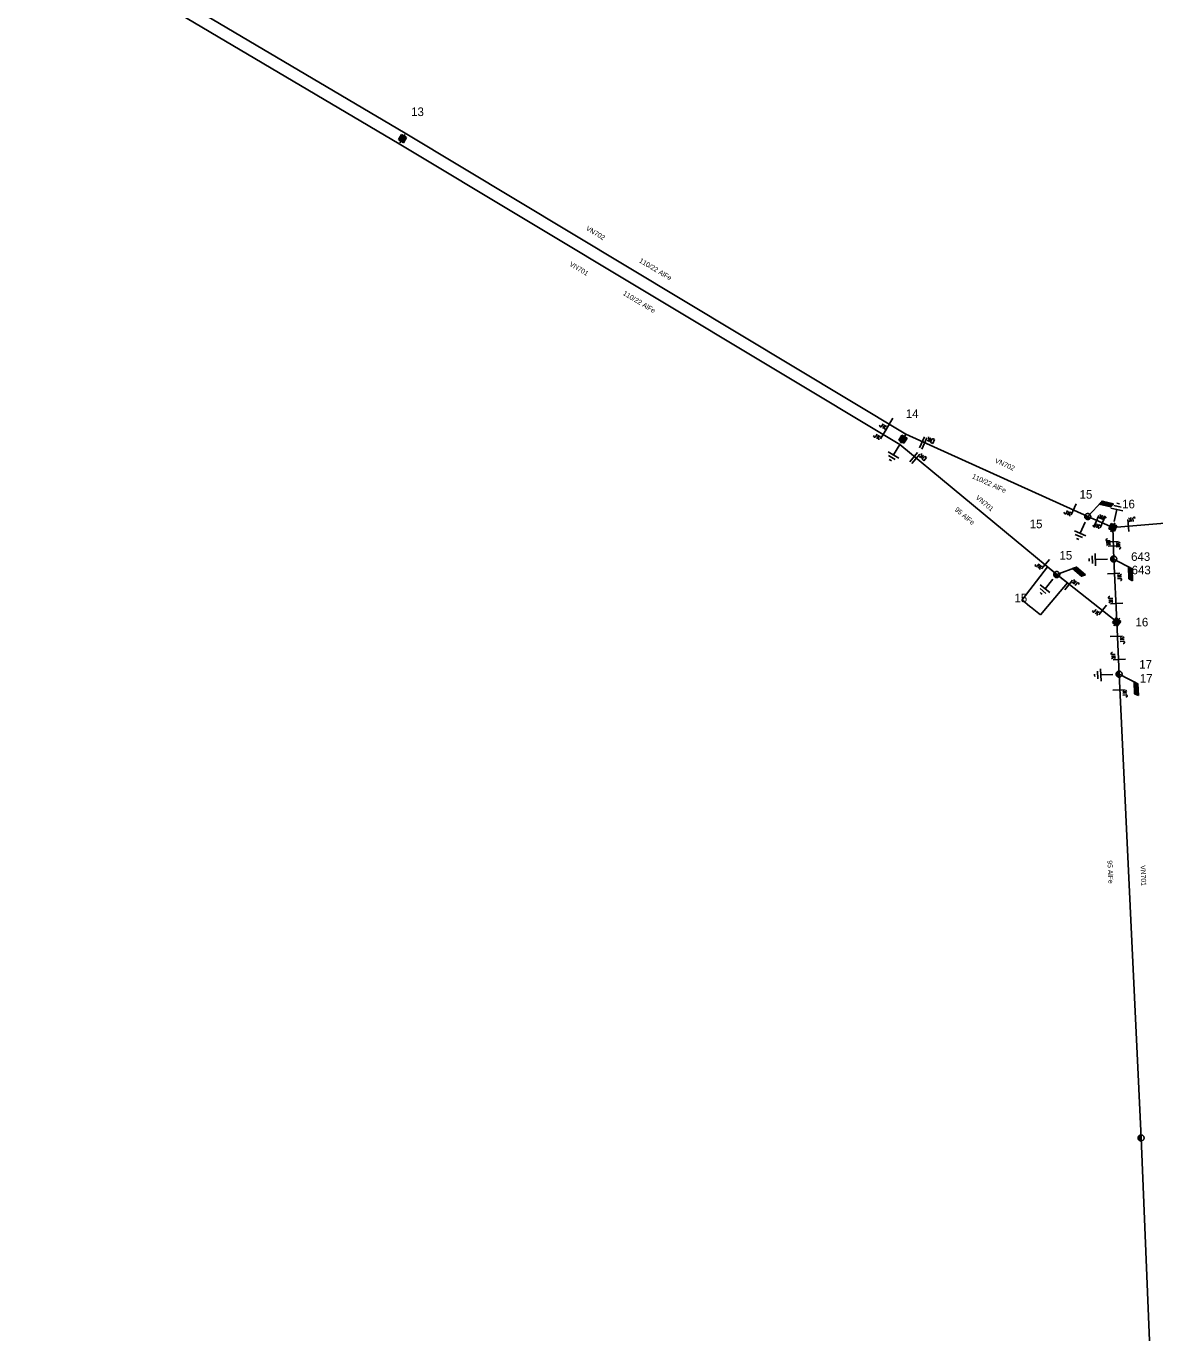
# Model space of a CAD drawing. Extents: x -545588 to -543214, y -1196037 to -1194452.
# Drawn here: x -543827.7 to -543597.4, y -1196037.4 to -1195769.1 of the extents above; entities that cross this region are included whole.
import ezdxf

# ---------------------------------------------------------------- set-up
doc = ezdxf.new("R2010")
doc.units = 0
for name, color, linetype in [('Default', 7, 'Continuous'), ('Vrstva 1', 7, 'Continuous'), ('Vrstva 11', 7, 'Continuous'), ('Vrstva 12', 7, 'Continuous'), ('Vrstva 13', 7, 'Continuous'), ('Vrstva 14', 7, 'Continuous'), ('Vrstva 15', 7, 'Continuous'), ('Vrstva 18', 7, 'Continuous'), ('Vrstva 2', 7, 'Continuous'), ('Vrstva 3', 7, 'Continuous'), ('Vrstva 35', 7, 'Continuous'), ('Vrstva 52', 7, 'Continuous')]:
    doc.layers.add(name, color=color, linetype=linetype)

# ---------------------------------------------------------------- blocks, each defined once
blk = doc.blocks.new('VN850')
at = {"layer": 'Vrstva 15'}
for points in [[(-0.56, 1.43), (-0.56, -1.07)], [(-0.01, 1.43), (-0.01, -1.07)], [(-2.09, -0.54), (-1.78, -0.54)], [(-2.09, -1.41), (-2.09, -0.54)], [(-1.78, -1.41), (-2.09, -1.41)], [(-1.78, -0.54), (-1.66, -0.6)], [(-1.67, -1.35), (-1.78, -1.41)], [(-1.59, -1.2), (-1.67, -1.35)], [(-1.66, -0.6), (-1.59, -0.75)], [(-1.59, -0.75), (-1.55, -0.96)], [(-1.55, -0.96), (-1.59, -1.2)], [(-1.26, -0.54), (-1.26, -1.41)], [(-0.85, -0.54), (-1.26, -1.09)], [(-1.13, -0.92), (-0.77, -1.41)]]:
    blk.add_lwpolyline(points, dxfattribs=at)
blk = doc.blocks.new('VN840')
at = {"layer": 'Vrstva 15'}
for points in [[(-0.01, 1.41), (-0.01, -1.09)], [(-1.51, -1.24), (-1.51, -1.15)], [(-1.48, -1.35), (-1.51, -1.24)], [(-1.33, -1.42), (-1.48, -1.35)], [(-1.27, -1.42), (-1.33, -1.42)], [(-1.13, -1.35), (-1.27, -1.42)], [(-1.09, -1.24), (-1.13, -1.35)], [(-1.09, -0.59), (-1.09, -1.24)], [(-0.68, -0.59), (-0.68, -1.42)], [(-0.68, -1.11), (-0.27, -0.59)], [(-0.54, -0.94), (-0.2, -1.42)]]:
    blk.add_lwpolyline(points, dxfattribs=at)
blk = doc.blocks.new('VN440')
at = {"layer": 'Vrstva 2'}
for points in [[(1.22, 0), (1.21, 0.13), (1.19, 0.25), (1.16, 0.38), (1.11, 0.5), (1.05, 0.61), (0.98, 0.72), (0.9, 0.82), (0.81, 0.91), (0.71, 0.99), (0.6, 1.06), (0.49, 1.12), (0.37, 1.16), (0.25, 1.2), (0.12, 1.22), (-0.01, 1.22), (-0.14, 1.22), (-0.26, 1.2), (-0.39, 1.16), (-0.51, 1.12), (-0.62, 1.06), (-0.73, 0.99), (-0.83, 0.91), (-0.92, 0.82), (-1, 0.72), (-1.07, 0.61), (-1.13, 0.5), (-1.18, 0.38), (-1.21, 0.25), (-1.23, 0.13), (-1.24, 0), (-1.23, -0.13), (-1.21, -0.26), (-1.18, -0.38), (-1.13, -0.5), (-1.07, -0.62), (-1, -0.73), (-0.92, -0.83), (-0.83, -0.92), (-0.73, -1), (-0.62, -1.07), (-0.51, -1.13), (-0.39, -1.17), (-0.26, -1.2), (-0.14, -1.23), (-0.01, -1.23), (0.12, -1.23), (0.25, -1.2), (0.37, -1.17), (0.49, -1.13), (0.6, -1.07), (0.71, -1), (0.81, -0.92), (0.9, -0.83), (0.98, -0.73), (1.05, -0.62), (1.11, -0.5), (1.16, -0.38), (1.19, -0.26), (1.21, -0.13), (1.22, 0)], [(-1.24, 0), (1.22, 0)], [(-1.18, -0.34), (1.1, -0.34)], [(-1.01, -0.63), (0.97, -0.63)], [(-0.74, -0.92), (0.68, -0.92)]]:
    blk.add_lwpolyline(points, dxfattribs=at)
blk = doc.blocks.new('VN810')
at = {"layer": 'Vrstva 14'}
for points in [[(0, -1.25), (0, -3.75)], [(1.25, -3.75), (-1.25, -3.75)], [(0.77, -4.37), (-0.8, -4.37)], [(0, -5), (-0.25, -5)], [(0.27, -5), (0, -5)]]:
    blk.add_lwpolyline(points, dxfattribs=at)
blk = doc.blocks.new('VN001')
at = {"layer": 'Default'}
for p, q in [((1.73, 3.03), (4.14, 3.03)), ((1.76, 3.08), (4.17, 3.08)), ((1.79, 3.13), (4.2, 3.13)), ((1.82, 3.18), (4.23, 3.18)), ((1.85, 3.23), (4.26, 3.23)), ((1.87, 3.28), (4.29, 3.28)), ((1.9, 3.33), (4.32, 3.33)), ((1.93, 3.38), (4.35, 3.38)), ((1.96, 3.43), (4.37, 3.43)), ((1.99, 3.48), (4.4, 3.48)), ((2.02, 3.53), (4.43, 3.53)), ((2.05, 3.58), (4.46, 3.58)), ((2.07, 3.63), (4.49, 3.63)), ((2.1, 3.68), (4.52, 3.68)), ((2.13, 3.73), (2.54, 3.73))]:
    blk.add_line(p, q, dxfattribs=at)
blk.add_lwpolyline([(2.13, 3.73), (0, 0)], dxfattribs=at)
blk.add_lwpolyline([(4.55, 3.73), (2.13, 3.73), (1.7, 2.98), (4.12, 2.99)], close=True, dxfattribs=at)
blk = doc.blocks.new('VN470')
at = {"layer": 'Vrstva 2'}
for points in [[(-1.23, 1.22), (1.23, 1.22)], [(-1.23, -1.23), (-1.23, 1.22)], [(-0.92, 0.9), (0.92, 0.9)], [(-0.92, -0.95), (-0.92, 0.9)], [(-0.61, 0.61), (0.61, 0.61)], [(-0.61, -0.62), (-0.61, 0.61)], [(-0.31, -0.27), (-0.31, 0.34)], [(-0.31, 0.34), (0.31, 0.34)], [(0, 1.22), (0, 1.97)], [(0.31, 0.34), (0.31, -0.27)], [(0.61, 0.61), (0.61, -0.62)], [(0.92, 0.9), (0.92, -0.95)], [(1.23, 1.22), (1.23, -1.23)], [(1.23, -1.23), (-1.23, -1.23)], [(0.92, -0.95), (-0.92, -0.95)], [(0.61, -0.62), (-0.61, -0.62)], [(0.31, -0.27), (-0.31, -0.27)], [(0, -1.23), (0, -1.98)]]:
    blk.add_lwpolyline(points, dxfattribs=at)

msp = doc.modelspace()

# ---------------------------------------------------------------- linework, layer by layer
at = {"layer": 'Vrstva 1'}
for points in [[(-545087.98, -1194964.09), (-544969.35, -1195068.41), (-544833.03, -1195149.76), (-544688.41, -1195235.46), (-544556.36, -1195314.32), (-544420.24, -1195394.62), (-544279.84, -1195477.88), (-544141.02, -1195559.94), (-544005.67, -1195639.57), (-543873.94, -1195717.89), (-543750.35, -1195790.92), (-543648.17, -1195852.31)], [(-543649.39, -1195854.44), (-543751.62, -1195793.1), (-543875.2, -1195719.97), (-544006.92, -1195641.71), (-544142.24, -1195562.12), (-544281.11, -1195480), (-544421.5, -1195396.73), (-544557.6, -1195316.44), (-544689.64, -1195237.57), (-544834.28, -1195151.89), (-544970.6, -1195070.55), (-545089.61, -1194965.95)], [(-543605.91, -1195871.36), (-543527.67, -1195864.84), (-543432.77, -1195857.32), (-543323.46, -1195848.64), (-543214.01, -1195839.86)], [(-543648.17, -1195852.31), (-543611.03, -1195869.16)], [(-543617.36, -1195881), (-543649.39, -1195854.44)], [(-543611.03, -1195869.16), (-543605.91, -1195871.36)], [(-543605.11, -1195890.68), (-543617.36, -1195881)], [(-543604.63, -1195901.33), (-543605.11, -1195890.68)], [(-543598.42, -1196037.4), (-543600.15, -1195996.01), (-543604.63, -1195901.33)]]:
    msp.add_lwpolyline(points, dxfattribs=at)
at = {"layer": 'Vrstva 35'}
msp.add_lwpolyline([(-543620.7, -1195889.19), (-543622.71, -1195887.61), (-543622.84, -1195887.5), (-543624.45, -1195886.17), (-543619.23, -1195879.45), (-543617.36, -1195881), (-543615.19, -1195882.72), (-543619.26, -1195887.5)], close=True, dxfattribs=at)
at = {"layer": 'Vrstva 52'}
for points in [[(-543605.91, -1195871.36), (-543605.73, -1195877.83)], [(-543605.73, -1195877.83), (-543605.11, -1195890.68)]]:
    msp.add_lwpolyline(points, dxfattribs=at)

# ---------------------------------------------------------------- block references
at = {"layer": 'Vrstva 11'}
for p, rotation in [((-543611.03, -1195869.16), -13.05202785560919), ((-543617.36, -1195881), -39.670955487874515), ((-543605.73, -1195877.83), -88.40301664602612), ((-543604.63, -1195901.33), -87.43911945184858)]:
    msp.add_blockref('VN001', p, dxfattribs=dict(at, rotation=rotation))
at = {"layer": 'Vrstva 13'}
for name, p, xscale, yscale, rotation in [('VN470', (-543750.92, -1195792), 0.49999999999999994, 0.5, 149.0160277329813), ('VN470', (-543648.75, -1195853.35), 0.5, 0.5, -30.98348877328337), ('VN440', (-543611.03, -1195869.16), 0.5, 0.5, -24.396491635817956), ('VN470', (-543605.91, -1195871.36), 0.5, 0.5, -23.261608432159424), ('VN440', (-543605.73, -1195877.83), 0.49999999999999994, 0.5, -88.40873060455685), ('VN440', (-543617.36, -1195881), 0.5, 0.5, -39.67067774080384), ('VN470', (-543605.11, -1195890.68), 0.49999999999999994, 0.5000000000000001, -38.31669718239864), ('VN440', (-543604.63, -1195901.33), 0.5000000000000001, 0.4999999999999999, -87.4335499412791), ('VN440', (-543600.15, -1195996.01), 0.5000000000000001, 0.5, -87.29079453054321)]:
    msp.add_blockref(name, p, dxfattribs=dict(at, xscale=xscale, yscale=yscale, rotation=rotation))
at = {"layer": 'Vrstva 15'}
for p, rotation in [((-543648.75, -1195853.35), -30.983391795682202), ((-543605.91, -1195871.36), 167.3754416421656), ((-543611.03, -1195869.16), -24.396991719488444), ((-543605.73, -1195877.83), -88.40952778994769), ((-543617.36, -1195881), -39.6711138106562), ((-543604.63, -1195901.33), -87.43419719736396)]:
    msp.add_blockref('VN810', p, dxfattribs=dict(at, rotation=rotation))
at = {"layer": 'Vrstva 18'}
for name, p, rotation in [('VN840', (-543651.55, -1195850.29), -31.001511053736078), ('VN840', (-543652.79, -1195852.39), -31.001511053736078), ('VN850', (-543644.81, -1195853.84), 155.60301665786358), ('VN850', (-543646.44, -1195856.88), 140.32877214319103), ('VN840', (-543613.94, -1195867.84), -24.39698334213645), ('VN840', (-543608.04, -1195870.44), -23.252591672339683), ('VN840', (-543609.23, -1195869.93), 156.74740832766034), ('VN840', (-543602.79, -1195870.83), -175.44626947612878), ('VN840', (-543605.8, -1195875.2), -88.40066669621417), ('VN840', (-543605.83, -1195874.24), 91.59023606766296), ('VN840', (-543619.74, -1195879.02), -39.67122785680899), ('VN840', (-543614.83, -1195883), 141.6840666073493), ('VN840', (-543605.59, -1195880.76), 92.76232223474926), ('VN840', (-543608.07, -1195888.34), -38.315933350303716), ('VN840', (-543605.29, -1195886.93), -87.23767776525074), ('VN840', (-543605.03, -1195893.59), 92.7108445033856), ('VN840', (-543604.76, -1195898.37), -87.42202774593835), ('VN840', (-543604.48, -1195904.54), 92.70188333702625)]:
    msp.add_blockref(name, p, dxfattribs=dict(at, rotation=rotation))

# ---------------------------------------------------------------- texts
at = {"layer": 'Vrstva 12'}
for s, p in [('15', (-543622.88, -1195871.53)), ('643', (-543602.07, -1195880.94)), ('15', (-543626, -1195886.65)), ('17', (-543600.4, -1195903.06))]:
    msp.add_text(s, height=1.75, dxfattribs=at).set_placement(p)
at = {"layer": 'Vrstva 14'}
for s, p in [('13', (-543749.15, -1195787.4)), ('14', (-543648.18, -1195849.05)), ('15', (-543612.69, -1195865.51)), ('16', (-543604.01, -1195867.48)), ('15', (-543616.8, -1195877.95)), ('643', (-543602.18, -1195878.21)), ('16', (-543601.28, -1195891.58)), ('17', (-543600.51, -1195900.2))]:
    msp.add_text(s, height=1.75, dxfattribs=at).set_placement(p)
at = {"layer": 'Vrstva 2'}
for s, rotation, p in [('110/22 AlFe', 328.998, (-543702.71, -1195817.18)), ('110/22 AlFe', 329.037, (-543706.02, -1195823.85)), ('110/22 AlFe', 335.603, (-543634.75, -1195861.29)), ('95 AlFe', 320.329, (-543638.28, -1195867.9)), ('95 AlFe', 272.709, (-543607.02, -1195939.36))]:
    msp.add_text(s, height=1, rotation=rotation, dxfattribs=at).set_placement(p)
at = {"layer": 'Vrstva 3'}
for s, rotation, p in [('VN702', 328.998, (-543713.56, -1195810.61)), ('VN701', 329.037, (-543716.94, -1195817.9)), ('VN702', 335.603, (-543630.06, -1195858.09)), ('VN701', 320.329, (-543634, -1195865.47)), ('VN701', 272.709, (-543600.25, -1195940.36))]:
    msp.add_text(s, height=1, rotation=rotation, dxfattribs=at).set_placement(p)

doc.saveas('drawing.dxf')
